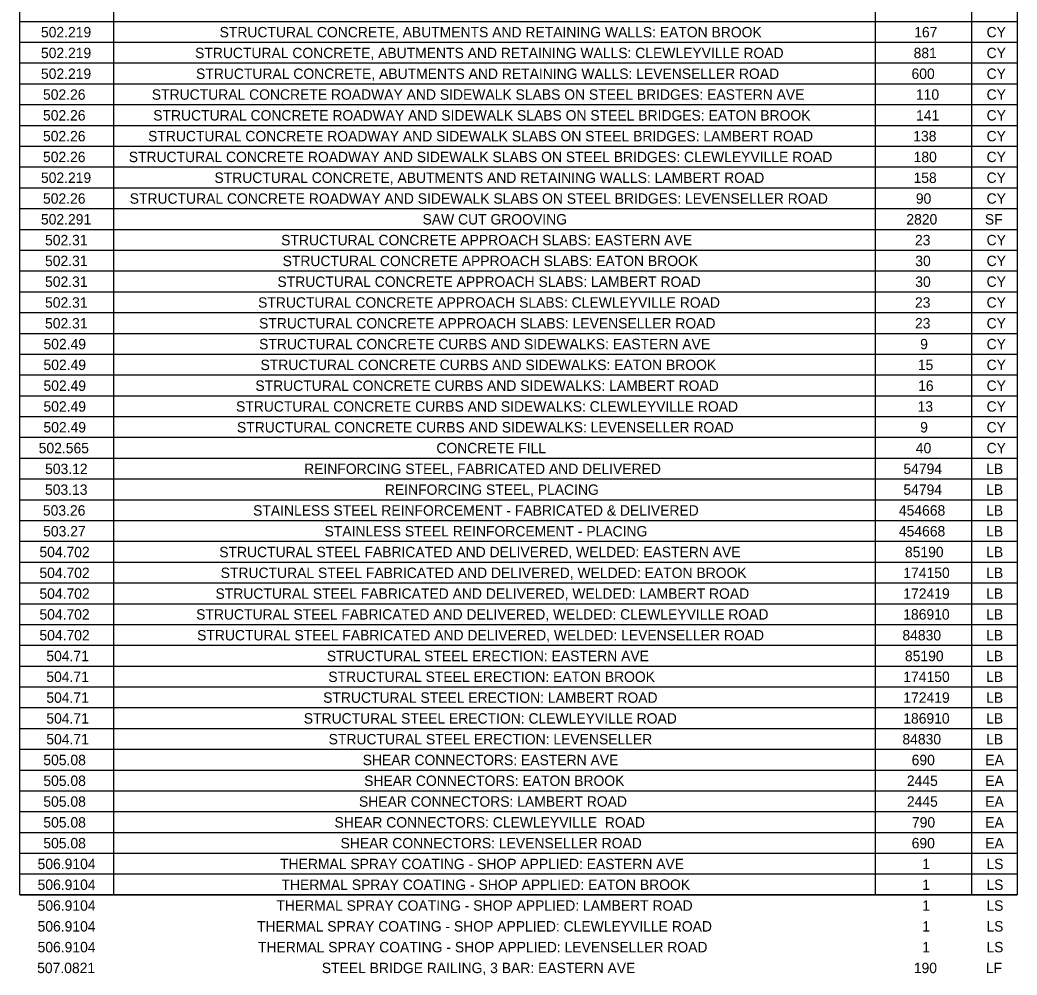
# Model space of a CAD drawing. Extents: x -18.7 to 5.6, y -2.7 to 5.1.
# Drawn here: x -18.69 to -17.746, y 2.166 to 3.071 of the extents above; entities that cross this region are included whole.
import ezdxf

# ---------------------------------------------------------------- set-up
doc = ezdxf.new("R2010")
doc.units = 0
doc.layers.add('ANNOTATION', color=7, linetype='Continuous')
doc.layers.add('BORDER', color=7, linetype='Continuous')

msp = doc.modelspace()

# ---------------------------------------------------------------- linework, layer by layer
at = {"layer": 'BORDER'}
for p, q in [((-18.60174, 3.9551), (-18.60174, 2.24242)), ((-17.88042, 3.9551), (-17.88042, 2.24242)), ((-17.78903, 3.9551), (-17.78903, 2.24242)), ((-18.69032, 3.06923), (-17.74604, 3.06923)), ((-18.69032, 3.04955), (-17.74604, 3.04955)), ((-18.69032, 3.02986), (-17.74604, 3.02986)), ((-18.69032, 3.01017), (-17.74604, 3.01017)), ((-18.69032, 2.99049), (-17.74604, 2.99049)), ((-18.69032, 2.9708), (-17.74604, 2.9708)), ((-18.69032, 2.95112), (-17.74604, 2.95112)), ((-18.69032, 2.93143), (-17.74604, 2.93143)), ((-18.69032, 2.91174), (-17.74604, 2.91174)), ((-18.69032, 2.89206), (-17.74604, 2.89206)), ((-18.69032, 2.87237), (-17.74604, 2.87237)), ((-18.69032, 2.85269), (-17.74604, 2.85269)), ((-18.69032, 2.833), (-17.74604, 2.833)), ((-18.69032, 2.81331), (-17.74604, 2.81331)), ((-18.69032, 2.79363), (-17.74604, 2.79363)), ((-18.69032, 2.77394), (-17.74604, 2.77394)), ((-18.69032, 2.75426), (-17.74604, 2.75426)), ((-18.69032, 2.73457), (-17.74604, 2.73457)), ((-18.69032, 2.71488), (-17.74604, 2.71488)), ((-18.69032, 2.6952), (-17.74604, 2.6952)), ((-18.69032, 2.67551), (-17.74604, 2.67551)), ((-18.69032, 2.65583), (-17.74604, 2.65583)), ((-18.69032, 2.63614), (-17.74604, 2.63614)), ((-18.69032, 2.61645), (-17.74604, 2.61645)), ((-18.69032, 2.59677), (-17.74604, 2.59677)), ((-18.69032, 2.57708), (-17.74604, 2.57708)), ((-18.69032, 2.5574), (-17.74604, 2.5574)), ((-18.69032, 2.53771), (-17.74604, 2.53771)), ((-18.69032, 2.51802), (-17.74604, 2.51802)), ((-18.69032, 2.49834), (-17.74604, 2.49834)), ((-18.69032, 2.47865), (-17.74604, 2.47865)), ((-18.69032, 2.45897), (-17.74604, 2.45897)), ((-18.69032, 2.43928), (-17.74604, 2.43928)), ((-18.69032, 2.41959), (-17.74604, 2.41959)), ((-18.69032, 2.39991), (-17.74604, 2.39991)), ((-18.69032, 2.38022), (-17.74604, 2.38022)), ((-18.69032, 2.36054), (-17.74604, 2.36054)), ((-18.69032, 2.34085), (-17.74604, 2.34085)), ((-18.69032, 2.32116), (-17.74604, 2.32116)), ((-18.69032, 2.30148), (-17.74604, 2.30148)), ((-18.69032, 2.28179), (-17.74604, 2.28179)), ((-18.69032, 2.26211), (-17.74604, 2.26211)), ((-18.69032, 2.24242), (-17.74604, 2.24242))]:
    msp.add_line(p, q, dxfattribs=at)
msp.add_lwpolyline([(-18.69032, 3.97479), (-17.74604, 3.97479), (-17.74604, 2.24242), (-18.69032, 2.24242)], close=True, dxfattribs=at)

# ---------------------------------------------------------------- texts
at = {"layer": 'ANNOTATION'}
for s, height, p in [('502.219', 0.009843, (-18.67043, 3.05414)), ('STRUCTURAL CONCRETE, ABUTMENTS AND RETAINING WALLS: EATON BROOK', 0.009843, (-18.50123, 3.05414)), ('167', 0.009843, (-17.84343, 3.05414)), ('CY', 0.009843, (-17.77487, 3.05414)), ('502.219', 0.009843, (-18.67043, 3.03446)), ('STRUCTURAL CONCRETE, ABUTMENTS AND RETAINING WALLS: CLEWLEYVILLE ROAD', 0.009843, (-18.52445, 3.03446)), ('881', 0.009843, (-17.84398, 3.03446)), ('CY', 0.009843, (-17.77487, 3.03446)), ('502.219', 0.009843, (-18.67043, 3.01477)), ('STRUCTURAL CONCRETE, ABUTMENTS AND RETAINING WALLS: LEVENSELLER ROAD', 0.009843, (-18.52355, 3.01477)), ('600', 0.009843, (-17.84599, 3.01477)), ('CY', 0.009843, (-17.77487, 3.01477)), ('502.26', 0.009843, (-18.66849, 2.99508)), ('STRUCTURAL CONCRETE ROADWAY AND SIDEWALK SLABS ON STEEL BRIDGES: EASTERN AVE', 0.009843, (-18.56542, 2.99508)), ('110', 0.009843, (-17.84181, 2.99508)), ('CY', 0.009843, (-17.77487, 2.99508)), ('502.26', 0.009843, (-18.66849, 2.9754)), ('STRUCTURAL CONCRETE ROADWAY AND SIDEWALK SLABS ON STEEL BRIDGES: EATON BROOK', 0.009843, (-18.56407, 2.9754)), ('141', 0.009843, (-17.84165, 2.9754)), ('CY', 0.009843, (-17.77487, 2.9754)), ('502.26', 0.009843, (-18.66849, 2.95571)), ('STRUCTURAL CONCRETE ROADWAY AND SIDEWALK SLABS ON STEEL BRIDGES: LAMBERT ROAD', 0.009843, (-18.56896, 2.95571)), ('138', 0.009843, (-17.84432, 2.95571)), ('CY', 0.009843, (-17.77487, 2.95571)), ('502.26', 0.009843, (-18.66849, 2.93603)), ('STRUCTURAL CONCRETE ROADWAY AND SIDEWALK SLABS ON STEEL BRIDGES: CLEWLEYVILLE ROAD', 0.009843, (-18.58728, 2.93603)), ('180', 0.009843, (-17.84398, 2.93603)), ('CY', 0.009843, (-17.77487, 2.93603)), ('502.219', 0.009843, (-18.67043, 2.91634)), ('STRUCTURAL CONCRETE, ABUTMENTS AND RETAINING WALLS: LAMBERT ROAD', 0.009843, (-18.50612, 2.91634)), ('158', 0.009843, (-17.84409, 2.91634)), ('CY', 0.009843, (-17.77487, 2.91634)), ('502.26', 0.009843, (-18.66849, 2.89665)), ('STRUCTURAL CONCRETE ROADWAY AND SIDEWALK SLABS ON STEEL BRIDGES: LEVENSELLER ROAD', 0.009843, (-18.58639, 2.89665)), ('90', 0.009843, (-17.84189, 2.89665)), ('CY', 0.009843, (-17.77487, 2.89665)), ('502.291', 0.009843, (-18.67043, 2.87697)), ('SAW CUT GROOVING', 0.009843, (-18.30904, 2.87697)), ('2820', 0.009843, (-17.85087, 2.87697)), ('SF', 0.009843, (-17.7765, 2.87697)), ('502.31', 0.009843, (-18.66656, 2.85728)), ('STRUCTURAL CONCRETE APPROACH SLABS: EASTERN AVE', 0.009843, (-18.44292, 2.85728)), ('23', 0.009843, (-17.8427, 2.85728)), ('CY', 0.009843, (-17.77487, 2.85728)), ('502.31', 0.009843, (-18.66656, 2.8376)), ('STRUCTURAL CONCRETE APPROACH SLABS: EATON BROOK', 0.009843, (-18.44156, 2.8376)), ('30', 0.009843, (-17.84243, 2.8376)), ('CY', 0.009843, (-17.77487, 2.8376)), ('502.31', 0.009843, (-18.66656, 2.81791)), ('STRUCTURAL CONCRETE APPROACH SLABS: LAMBERT ROAD', 0.009843, (-18.44646, 2.81791)), ('30', 0.009843, (-17.84243, 2.81791)), ('CY', 0.009843, (-17.77487, 2.81791)), ('502.31', 0.009843, (-18.66656, 2.79822)), ('STRUCTURAL CONCRETE APPROACH SLABS: CLEWLEYVILLE ROAD', 0.009843, (-18.46478, 2.79822)), ('23', 0.009843, (-17.8427, 2.79822)), ('CY', 0.009843, (-17.77487, 2.79822)), ('502.31', 0.009843, (-18.66656, 2.77854)), ('STRUCTURAL CONCRETE APPROACH SLABS: LEVENSELLER ROAD', 0.009843, (-18.46388, 2.77854)), ('23', 0.009843, (-17.8427, 2.77854)), ('CY', 0.009843, (-17.77487, 2.77854)), ('502.49', 0.009843, (-18.66803, 2.75885)), ('STRUCTURAL CONCRETE CURBS AND SIDEWALKS: EASTERN AVE', 0.009843, (-18.46383, 2.75885)), ('9', 0.00984, (-17.83778, 2.75885)), ('CY', 0.009843, (-17.77487, 2.75885)), ('502.49', 0.009843, (-18.66803, 2.73917)), ('STRUCTURAL CONCRETE CURBS AND SIDEWALKS: EATON BROOK', 0.009843, (-18.46247, 2.73917)), ('15', 0.009843, (-17.83999, 2.73917)), ('CY', 0.009843, (-17.77487, 2.73917)), ('502.49', 0.009843, (-18.66803, 2.71948)), ('STRUCTURAL CONCRETE CURBS AND SIDEWALKS: LAMBERT ROAD', 0.009843, (-18.46736, 2.71948)), ('16', 0.009843, (-17.83972, 2.71948)), ('CY', 0.009843, (-17.77487, 2.71948)), ('502.49', 0.009843, (-18.66803, 2.69979)), ('STRUCTURAL CONCRETE CURBS AND SIDEWALKS: CLEWLEYVILLE ROAD', 0.009843, (-18.48568, 2.69979)), ('13', 0.009843, (-17.84022, 2.69979)), ('CY', 0.009843, (-17.77487, 2.69979)), ('502.49', 0.009843, (-18.66803, 2.68011)), ('STRUCTURAL CONCRETE CURBS AND SIDEWALKS: LEVENSELLER ROAD', 0.009843, (-18.48479, 2.68011)), ('9', 0.00984, (-17.83778, 2.68011)), ('CY', 0.009843, (-17.77487, 2.68011)), ('502.565', 0.009843, (-18.67256, 2.66042)), ('CONCRETE FILL', 0.009843, (-18.29593, 2.66042)), ('40', 0.009843, (-17.84189, 2.66042)), ('CY', 0.009843, (-17.77487, 2.66042)), ('503.12', 0.009843, (-18.66652, 2.64074)), ('REINFORCING STEEL, FABRICATED AND DELIVERED', 0.009843, (-18.42119, 2.64074)), ('54794', 0.009843, (-17.85366, 2.64074)), ('LB', 0.009843, (-17.7753, 2.64074)), ('503.13', 0.009843, (-18.66659, 2.62105)), ('REINFORCING STEEL, PLACING', 0.009843, (-18.34473, 2.62105)), ('54794', 0.009843, (-17.85366, 2.62105)), ('LB', 0.009843, (-17.7753, 2.62105)), ('503.26', 0.009843, (-18.66857, 2.60136)), ('STAINLESS STEEL REINFORCEMENT - FABRICATED & DELIVERED', 0.009843, (-18.4695, 2.60136)), ('454668', 0.009843, (-17.85796, 2.60136)), ('LB', 0.009843, (-17.7753, 2.60136)), ('503.27', 0.009843, (-18.66834, 2.58168)), ('STAINLESS STEEL REINFORCEMENT - PLACING', 0.009843, (-18.40184, 2.58168)), ('454668', 0.009843, (-17.85796, 2.58168)), ('LB', 0.009843, (-17.7753, 2.58168)), ('504.702', 0.009843, (-18.67187, 2.56199)), ('STRUCTURAL STEEL FABRICATED AND DELIVERED, WELDED: EASTERN AVE', 0.009843, (-18.50157, 2.56199)), ('85190', 0.009843, (-17.85219, 2.56199)), ('LB', 0.009843, (-17.7753, 2.56199)), ('504.702', 0.009843, (-18.67187, 2.54231)), ('STRUCTURAL STEEL FABRICATED AND DELIVERED, WELDED: EATON BROOK', 0.009843, (-18.50021, 2.54231)), ('174150', 0.009843, (-17.85374, 2.54231)), ('LB', 0.009843, (-17.7753, 2.54231)), ('504.702', 0.009843, (-18.67187, 2.52262)), ('STRUCTURAL STEEL FABRICATED AND DELIVERED, WELDED: LAMBERT ROAD', 0.009843, (-18.5051, 2.52262)), ('172419', 0.009843, (-17.85374, 2.52262)), ('LB', 0.009843, (-17.7753, 2.52262)), ('504.702', 0.009843, (-18.67187, 2.50293)), ('STRUCTURAL STEEL FABRICATED AND DELIVERED, WELDED: CLEWLEYVILLE ROAD', 0.009843, (-18.52342, 2.50293)), ('186910', 0.009843, (-17.85381, 2.50293)), ('LB', 0.009843, (-17.7753, 2.50293)), ('504.702', 0.009843, (-18.67187, 2.48325)), ('STRUCTURAL STEEL FABRICATED AND DELIVERED, WELDED: LEVENSELLER ROAD', 0.009843, (-18.52253, 2.48325)), ('84830', 0.009843, (-17.85459, 2.48325)), ('LB', 0.009843, (-17.7753, 2.48325)), ('504.71', 0.009843, (-18.66532, 2.46356)), ('STRUCTURAL STEEL ERECTION: EASTERN AVE', 0.009843, (-18.39965, 2.46356)), ('85190', 0.009843, (-17.85219, 2.46356)), ('LB', 0.009843, (-17.7753, 2.46356)), ('504.71', 0.009843, (-18.66532, 2.44388)), ('STRUCTURAL STEEL ERECTION: EATON BROOK', 0.009843, (-18.39829, 2.44388)), ('174150', 0.009843, (-17.85374, 2.44388)), ('LB', 0.009843, (-17.7753, 2.44388)), ('504.71', 0.009843, (-18.66532, 2.42419)), ('STRUCTURAL STEEL ERECTION: LAMBERT ROAD', 0.009843, (-18.40318, 2.42419)), ('172419', 0.009843, (-17.85374, 2.42419)), ('LB', 0.009843, (-17.7753, 2.42419)), ('504.71', 0.009843, (-18.66532, 2.4045)), ('STRUCTURAL STEEL ERECTION: CLEWLEYVILLE ROAD', 0.009843, (-18.42151, 2.4045)), ('186910', 0.009843, (-17.85381, 2.4045)), ('LB', 0.009843, (-17.7753, 2.4045)), ('504.71', 0.009843, (-18.66532, 2.38482)), ('STRUCTURAL STEEL ERECTION: LEVENSELLER', 0.009843, (-18.39798, 2.38482)), ('84830', 0.009843, (-17.85459, 2.38482)), ('LB', 0.009843, (-17.7753, 2.38482)), ('505.08', 0.009843, (-18.66815, 2.36513)), ('SHEAR CONNECTORS: EASTERN AVE', 0.009843, (-18.36571, 2.36513)), ('690', 0.009843, (-17.84584, 2.36513)), ('EA', 0.009843, (-17.77611, 2.36513)), ('505.08', 0.009843, (-18.66815, 2.34545)), ('SHEAR CONNECTORS: EATON BROOK', 0.009843, (-18.36435, 2.34545)), ('2445', 0.009843, (-17.85037, 2.34545)), ('EA', 0.009843, (-17.77611, 2.34545)), ('505.08', 0.009843, (-18.66815, 2.32576)), ('SHEAR CONNECTORS: LAMBERT ROAD', 0.009843, (-18.36925, 2.32576)), ('2445', 0.009843, (-17.85037, 2.32576)), ('EA', 0.009843, (-17.77611, 2.32576)), ('505.08', 0.009843, (-18.66815, 2.30607)), ('SHEAR CONNECTORS: CLEWLEYVILLE  ROAD', 0.009843, (-18.39245, 2.30607)), ('790', 0.009843, (-17.84561, 2.30607)), ('EA', 0.009843, (-17.77611, 2.30607)), ('505.08', 0.009843, (-18.66815, 2.28639)), ('SHEAR CONNECTORS: LEVENSELLER ROAD', 0.009843, (-18.38667, 2.28639)), ('690', 0.009843, (-17.84584, 2.28639)), ('EA', 0.009843, (-17.77611, 2.28639)), ('506.9104', 0.009843, (-18.6736, 2.2667)), ('THERMAL SPRAY COATING - SHOP APPLIED: EASTERN AVE', 0.009843, (-18.44395, 2.2667)), ('1', 0.00984, (-17.83576, 2.2667)), ('LS', 0.009843, (-17.77506, 2.2667)), ('506.9104', 0.009843, (-18.6736, 2.24702)), ('THERMAL SPRAY COATING - SHOP APPLIED: EATON BROOK', 0.009843, (-18.4426, 2.24702)), ('1', 0.00984, (-17.83576, 2.24702)), ('LS', 0.009843, (-17.77506, 2.24702)), ('506.9104', 0.009843, (-18.6736, 2.22733)), ('THERMAL SPRAY COATING - SHOP APPLIED: LAMBERT ROAD', 0.009843, (-18.44749, 2.22733)), ('1', 0.00984, (-17.83576, 2.22733)), ('LS', 0.009843, (-17.77506, 2.22733)), ('506.9104', 0.009843, (-18.6736, 2.20764)), ('THERMAL SPRAY COATING - SHOP APPLIED: CLEWLEYVILLE ROAD', 0.009843, (-18.46581, 2.20764)), ('1', 0.00984, (-17.83576, 2.20764)), ('LS', 0.009843, (-17.77506, 2.20764)), ('506.9104', 0.009843, (-18.6736, 2.18796)), ('THERMAL SPRAY COATING - SHOP APPLIED: LEVENSELLER ROAD', 0.009843, (-18.46491, 2.18796)), ('1', 0.00984, (-17.83576, 2.18796)), ('LS', 0.009843, (-17.77506, 2.18796)), ('507.0821', 0.009843, (-18.674, 2.16827)), ('STEEL BRIDGE RAILING, 3 BAR: EASTERN AVE', 0.009843, (-18.40447, 2.16827)), ('190', 0.009843, (-17.84382, 2.16827)), ('LF', 0.009843, (-17.77549, 2.16827))]:
    msp.add_text(s, height=height, dxfattribs=at).set_placement(p)

doc.saveas('drawing.dxf')
